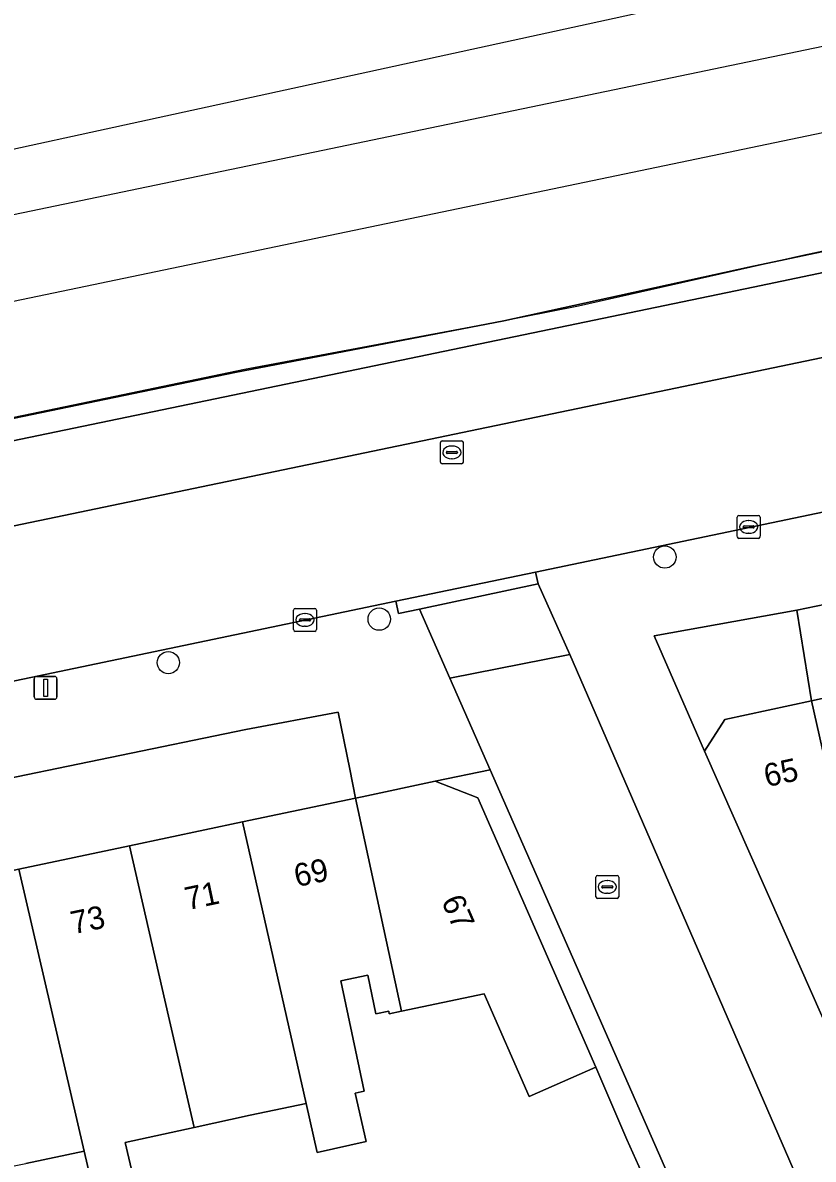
# Model space of a CAD drawing. Extents: x 162989 to 165008, y 383432 to 384338.
# Drawn here: x 163944.51 to 163979.07, y 384118.85 to 384168.55 of the extents above; entities that cross this region are included whole.
import ezdxf

# ---------------------------------------------------------------- set-up
doc = ezdxf.new("R2010")
doc.units = 0
for name, color, linetype in [('IMGEO_Boom', 7, 'Continuous'), ('IMGEO_Erf', 7, 'Continuous'), ('IMGEO_Geluidsscherm', 7, 'Continuous'), ('IMGEO_Groenvoorziening', 7, 'Continuous'), ('IMGEO_Haag', 7, 'Continuous'), ('IMGEO_Kolk', 7, 'Continuous'), ('IMGEO_Lichtmast', 7, 'Continuous'), ('IMGEO_Muur', 7, 'Continuous'), ('IMGEO_Pand', 7, 'Continuous'), ('IMGEO_Pand_nummerreeks', 7, 'Continuous'), ('IMGEO_Rijbaan_lokaal_gesloten', 7, 'Continuous'), ('IMGEO_Rijbaan_lokaal_open', 7, 'Continuous'), ('IMGEO_Rioolput', 7, 'Continuous'), ('IMGEO_Spoor', 7, 'Continuous'), ('IMGEO_Spoorbaan_halfverhard', 7, 'Continuous'), ('IMGEO_Voetpad_open', 7, 'Continuous')]:
    doc.layers.add(name, color=color, linetype=linetype)

msp = doc.modelspace()

# ---------------------------------------------------------------- linework, layer by layer
at = {"layer": 'IMGEO_Boom'}
for centre in [(163972.578, 384145.184), (163960.095, 384142.469), (163950.875, 384140.566)]:
    msp.add_circle(centre, 0.489, dxfattribs=at)
at = {"layer": 'IMGEO_Erf'}
for points in [[(163995.254, 384146.36), (163978.345, 384142.859), (163978.993, 384138.902), (163984.019, 384139.999)], [(163971.837, 384117.672), (163970.917, 384119.717), (163969.555, 384122.869), (163966.652, 384121.592), (163964.675, 384126.085), (163961.062, 384125.322), (163960.533, 384125.21), (163960.508, 384125.33), (163959.948, 384125.212), (163959.592, 384126.897), (163958.417, 384126.649), (163959.436, 384121.826), (163959.046, 384121.744), (163959.524, 384119.624), (163957.381, 384119.14), (163956.896, 384121.289), (163954.452, 384120.772), (163952.011, 384120.238), (163948.994, 384119.582), (163950.338, 384113.794)], [(163948.549, 384113.379), (163947.197, 384119.202), (163944.64, 384118.661)]]:
    msp.add_lwpolyline(points, dxfattribs=at)
for points in [[(163978.345, 384142.859), (163972.112, 384141.733), (163974.316, 384136.7), (163975.198, 384138.074), (163978.993, 384138.902)], [(163949.177, 384132.553), (163954.118, 384133.598), (163959.059, 384134.642), (163958.806, 384135.902), (163958.304, 384138.407), (163954.262, 384137.638), (163924.604, 384131.515), (163926.626, 384127.328), (163929.903, 384128.02), (163929.809, 384128.46), (163934.649, 384129.483), (163939.492, 384130.507), (163944.334, 384131.53)]]:
    msp.add_lwpolyline(points, close=True, dxfattribs=at)
at = {"layer": 'IMGEO_Geluidsscherm'}
msp.add_lwpolyline([(163937.597, 384149.952), (163949.238, 384152.367), (163954.207, 384153.399), (163965.198, 384155.461), (163968.809, 384156.168), (163978.614, 384158.383), (163993.212, 384161.496), (164003.071, 384163.567), (164007.919, 384164.566), (164017.762, 384166.559), (164027.578, 384168.478), (164032.408, 384169.426)], dxfattribs=at)
at = {"layer": 'IMGEO_Groenvoorziening'}
for points in [[(163892.745, 384139.603), (163976.433, 384156.982), (164073.867, 384177.406), (164173.737, 384197.907), (164238.498, 384211.23), (164245.279, 384212.748), (164245.015, 384213.611), (164238.302, 384212.109), (164224.204, 384209.495), (164191.357, 384202.662), (164184.194, 384201.103), (164173.545, 384198.786), (164138.86, 384191.809), (164106.067, 384184.851), (164073.689, 384178.288), (164040.716, 384171.257), (164027.429, 384168.427), (164008.211, 384164.605), (163976.248, 384157.863), (163965.539, 384155.519), (163953.785, 384153.248), (163943.293, 384151.084)], [(164073.867, 384177.406), (163976.433, 384156.982), (163892.745, 384139.603)], [(163916.336, 384140.767), (163989.771, 384156.06), (164000, 384158.405), (164008.393, 384160.13), (164013.045, 384161.087), (164068.214, 384172.427)]]:
    msp.add_lwpolyline(points, dxfattribs=at)
at = {"layer": 'IMGEO_Haag'}
msp.add_lwpolyline([(163892.745, 384139.603), (163976.433, 384156.982), (164073.867, 384177.406), (164173.737, 384197.907), (164238.498, 384211.23), (164245.279, 384212.748), (164245.015, 384213.611), (164238.302, 384212.109), (164224.204, 384209.495), (164191.357, 384202.662), (164184.194, 384201.103), (164173.545, 384198.786), (164138.86, 384191.809), (164106.067, 384184.851), (164073.689, 384178.288), (164040.716, 384171.257), (164027.429, 384168.427), (164008.211, 384164.605), (163976.248, 384157.863), (163965.539, 384155.519), (163953.785, 384153.248), (163943.293, 384151.084)], dxfattribs=at)
at = {"layer": 'IMGEO_Kolk'}
for p, q in [((163975.743, 384146.075), (163975.743, 384146.927)), ((163975.818, 384147.001), (163976.67, 384147.001)), ((163976.231, 384146.781), (163976.256, 384146.781)), ((163976.744, 384146.927), (163976.744, 384146.075)), ((163976.002, 384146.495), (163976.002, 384146.507)), ((163976.44, 384146.458), (163976.042, 384146.458)), ((163976.045, 384146.544), (163976.443, 384146.544)), ((163976.486, 384146.507), (163976.486, 384146.495)), ((163976.67, 384146.001), (163975.818, 384146.001)), ((163976.254, 384146.221), (163976.229, 384146.221)), ((163956.347, 384142.009), (163956.347, 384142.861)), ((163956.422, 384142.935), (163957.274, 384142.935)), ((163957.348, 384142.861), (163957.348, 384142.009)), ((163956.606, 384142.429), (163956.606, 384142.441)), ((163957.044, 384142.392), (163956.646, 384142.392)), ((163956.649, 384142.478), (163957.047, 384142.478)), ((163956.835, 384142.715), (163956.86, 384142.715)), ((163957.09, 384142.441), (163957.09, 384142.429)), ((163957.274, 384141.935), (163956.422, 384141.935)), ((163956.858, 384142.155), (163956.833, 384142.155)), ((163969.562, 384130.332), (163969.562, 384131.184)), ((163969.637, 384131.258), (163970.489, 384131.258)), ((163970.05, 384131.038), (163970.075, 384131.038)), ((163970.563, 384131.184), (163970.563, 384130.332)), ((163969.821, 384130.752), (163969.821, 384130.764)), ((163970.259, 384130.715), (163969.861, 384130.715)), ((163969.864, 384130.801), (163970.262, 384130.801)), ((163970.073, 384130.478), (163970.048, 384130.478)), ((163970.305, 384130.764), (163970.305, 384130.752)), ((163970.489, 384130.258), (163969.637, 384130.258))]:
    msp.add_line(p, q, dxfattribs=at)
for points in [[(163975.743, 384146.075), (163975.743, 384146.927)], [(163975.818, 384147.001), (163976.67, 384147.001)], [(163976.744, 384146.927), (163976.744, 384146.075)], [(163976.67, 384146.001), (163975.818, 384146.001)], [(163956.347, 384142.009), (163956.347, 384142.861)], [(163956.422, 384142.935), (163957.274, 384142.935)], [(163957.348, 384142.861), (163957.348, 384142.009)], [(163957.274, 384141.935), (163956.422, 384141.935)], [(163969.562, 384130.332), (163969.562, 384131.184)], [(163969.637, 384131.258), (163970.489, 384131.258)], [(163970.563, 384131.184), (163970.563, 384130.332)], [(163970.489, 384130.258), (163969.637, 384130.258)]]:
    msp.add_lwpolyline(points, dxfattribs=at)
for centre, radius, start, end in [((163975.82, 384146.925), 0.0765, 91.552, 178.448), ((163975.82, 384146.925), 0.0765, 91.552, 178.448), ((163976.668, 384146.925), 0.0765, 1.552, 88.448), ((163976.668, 384146.925), 0.0765, 1.552, 88.448), ((163976.042, 384146.504), 0.0403, 85.8775, 175.7526), ((163976.039, 384146.494), 0.0366, 178.938, 274.7102), ((163976.443, 384146.501), 0.043, 264.8664, 352.4533), ((163976.447, 384146.506), 0.0386, 1.7309, 96.639), ((163975.82, 384146.077), 0.0765, 181.552, 268.448), ((163975.82, 384146.077), 0.0765, 181.552, 268.448), ((163976.668, 384146.077), 0.0765, 271.552, 358.448), ((163976.668, 384146.077), 0.0765, 271.552, 358.448), ((163956.424, 384142.859), 0.0765, 91.552, 178.448), ((163956.424, 384142.859), 0.0765, 91.552, 178.448), ((163957.272, 384142.859), 0.0765, 1.552, 88.448), ((163957.272, 384142.859), 0.0765, 1.552, 88.448), ((163956.646, 384142.438), 0.0403, 85.8775, 175.7526), ((163956.643, 384142.428), 0.0366, 178.938, 274.7102), ((163957.047, 384142.435), 0.043, 264.8664, 352.4533), ((163957.051, 384142.44), 0.0386, 1.7309, 96.639), ((163956.424, 384142.011), 0.0765, 181.552, 268.448), ((163956.424, 384142.011), 0.0765, 181.552, 268.448), ((163957.272, 384142.011), 0.0765, 271.552, 358.448), ((163957.272, 384142.011), 0.0765, 271.552, 358.448), ((163969.639, 384131.182), 0.0765, 91.552, 178.448), ((163969.639, 384131.182), 0.0765, 91.552, 178.448), ((163970.487, 384131.182), 0.0765, 1.552, 88.448), ((163970.487, 384131.182), 0.0765, 1.552, 88.448), ((163969.861, 384130.761), 0.0403, 85.8775, 175.7526), ((163969.858, 384130.751), 0.0366, 178.938, 274.7102), ((163970.262, 384130.758), 0.043, 264.8664, 352.4533), ((163970.266, 384130.763), 0.0386, 1.7309, 96.639), ((163969.639, 384130.334), 0.0765, 181.552, 268.448), ((163969.639, 384130.334), 0.0765, 181.552, 268.448), ((163970.487, 384130.334), 0.0765, 271.552, 358.448), ((163970.487, 384130.334), 0.0765, 271.552, 358.448)]:
    msp.add_arc(centre, radius, start, end, dxfattribs=at)
for centre, major_axis, ratio, start_param, end_param in [((163976.23, 384146.501), (-0.387, 0.002), 0.722429, 4.712389, 7.853982), ((163976.255, 384146.501), (-0.39, 0.002), 0.717154, 1.570796, 4.712389), ((163956.834, 384142.435), (-0.387, 0.002), 0.722429, 4.712389, 7.853982), ((163956.859, 384142.435), (-0.39, 0.002), 0.717154, 1.570796, 4.712389), ((163970.049, 384130.758), (-0.387, 0.002), 0.722429, 4.712389, 7.853982), ((163970.074, 384130.758), (-0.39, 0.002), 0.717154, 1.570796, 4.712389)]:
    msp.add_ellipse(centre, major_axis=major_axis, ratio=ratio, start_param=start_param, end_param=end_param, dxfattribs=at)
at = {"layer": 'IMGEO_Lichtmast'}
for p, q in [((163945.017, 384139.065), (163945.017, 384139.865)), ((163945.017, 384139.865), (163945.017, 384139.065)), ((163945.117, 384139.965), (163945.907, 384139.965)), ((163945.907, 384139.965), (163945.117, 384139.965)), ((163946.007, 384139.865), (163946.007, 384139.065)), ((163946.007, 384139.065), (163946.007, 384139.865)), ((163945.907, 384138.965), (163945.117, 384138.965)), ((163945.117, 384138.965), (163945.907, 384138.965))]:
    msp.add_line(p, q, dxfattribs=at)
msp.add_lwpolyline([(163945.437, 384139.84), (163945.587, 384139.84), (163945.587, 384139.09), (163945.437, 384139.09), (163945.437, 384139.84)], dxfattribs=at)
for centre, start, end in [((163945.117, 384139.865), 90, 180), ((163945.117, 384139.865), 90, 180), ((163945.907, 384139.865), 0, 90), ((163945.907, 384139.865), 360, 90), ((163945.117, 384139.065), 180, 270), ((163945.117, 384139.065), 180, 270), ((163945.907, 384139.065), 270, 0), ((163945.907, 384139.065), 270, 0)]:
    msp.add_arc(centre, 0.1, start, end, dxfattribs=at)
at = {"layer": 'IMGEO_Muur'}
msp.add_lwpolyline([(163970.917, 384119.717), (163969.555, 384122.869)], dxfattribs=at)
at = {"layer": 'IMGEO_Pand'}
for points in [[(163978.993, 384138.902), (163981.792, 384126.471), (163982.507, 384126.59), (163983.979, 384126.835), (163984.175, 384126.868), (163983.735, 384128.885), (163986.074, 384129.395), (163984.973, 384135.075), (163984.019, 384139.999)], [(163978.993, 384138.902), (163975.198, 384138.074), (163974.316, 384136.7), (163979.046, 384126.015), (163981.004, 384121.592), (163984.214, 384122.729), (163982.507, 384126.59), (163981.792, 384126.471)], [(163961.062, 384125.322), (163964.675, 384126.085), (163966.652, 384121.592), (163969.555, 384122.869), (163964.399, 384134.653), (163962.536, 384135.377), (163959.347, 384134.703), (163959.059, 384134.642)], [(163959.059, 384134.642), (163954.118, 384133.598), (163956.896, 384121.289), (163957.381, 384119.14), (163959.524, 384119.624), (163959.046, 384121.744), (163959.436, 384121.826), (163958.417, 384126.649), (163959.592, 384126.897), (163959.948, 384125.212), (163960.508, 384125.33), (163960.533, 384125.21), (163961.062, 384125.322)], [(163956.896, 384121.289), (163954.118, 384133.598), (163949.177, 384132.553), (163950.89, 384125.108), (163952.011, 384120.238), (163954.452, 384120.772)], [(163949.177, 384132.553), (163944.334, 384131.53), (163947.197, 384119.202), (163948.549, 384113.379), (163950.338, 384113.794), (163948.994, 384119.582), (163952.011, 384120.238), (163950.89, 384125.108)], [(163939.492, 384130.507), (163941.215, 384123.033), (163942.328, 384118.204), (163944.64, 384118.661), (163947.197, 384119.202), (163944.334, 384131.53)]]:
    msp.add_lwpolyline(points, close=True, dxfattribs=at)
at = {"layer": 'IMGEO_Rijbaan_lokaal_gesloten'}
msp.add_lwpolyline([(163923.113, 384135.366), (163960.826, 384143.251), (163966.926, 384144.526), (163982.743, 384147.834), (163986.464, 384148.612), (163997.553, 384150.93), (164000, 384151.442), (164001.293, 384151.706), (164009.768, 384153.438), (164008.393, 384160.13), (164000, 384158.405), (163989.771, 384156.06), (163916.336, 384140.767), (163911.749, 384139.874), (163913.038, 384133.253), (163917.195, 384134.125)], close=True, dxfattribs=at)
at = {"layer": 'IMGEO_Rijbaan_lokaal_open'}
msp.add_lwpolyline([(163968.422, 384140.927), (163963.186, 384139.88), (163964.941, 384135.885), (163977.753, 384106.722), (163978.881, 384101.326), (163977.556, 384101.07), (163973.97, 384100.353), (163970.383, 384099.636), (163966.797, 384098.92), (163963.375, 384098.236), (163959.954, 384097.552), (163956.532, 384096.868), (163953.111, 384096.184), (163949.689, 384095.5), (163946.267, 384094.816), (163945.04, 384094.571), (163946.672, 384086.586), (163955.483, 384088.354), (163978.057, 384092.882), (163980.946, 384093.461), (163983.835, 384094.041), (163986.724, 384094.62), (163985.215, 384102.252)], close=True, dxfattribs=at)
at = {"layer": 'IMGEO_Rioolput'}
for p, q in [((163962.844, 384150.26), (163963.696, 384150.26)), ((163962.769, 384149.334), (163962.769, 384150.186)), ((163963.028, 384149.754), (163963.028, 384149.766)), ((163963.071, 384149.803), (163963.469, 384149.803)), ((163963.257, 384150.04), (163963.282, 384150.04)), ((163963.512, 384149.766), (163963.512, 384149.754)), ((163963.77, 384150.186), (163963.77, 384149.334)), ((163963.696, 384149.26), (163962.844, 384149.26)), ((163963.466, 384149.717), (163963.068, 384149.717)), ((163963.28, 384149.48), (163963.255, 384149.48))]:
    msp.add_line(p, q, dxfattribs=at)
for points in [[(163962.844, 384150.26), (163963.696, 384150.26)], [(163962.769, 384149.334), (163962.769, 384150.186)], [(163963.77, 384150.186), (163963.77, 384149.334)], [(163963.696, 384149.26), (163962.844, 384149.26)]]:
    msp.add_lwpolyline(points, dxfattribs=at)
for centre, radius, start, end in [((163962.846, 384150.184), 0.0765, 91.552, 178.448), ((163962.846, 384150.184), 0.0765, 91.552, 178.448), ((163963.694, 384150.184), 0.0765, 1.552, 88.448), ((163963.694, 384150.184), 0.0765, 1.552, 88.448), ((163963.068, 384149.763), 0.0403, 85.8775, 175.7526), ((163963.065, 384149.753), 0.0366, 178.938, 274.7102), ((163963.469, 384149.76), 0.043, 264.8664, 352.4533), ((163963.473, 384149.765), 0.0386, 1.7309, 96.639), ((163962.846, 384149.336), 0.0765, 181.552, 268.448), ((163962.846, 384149.336), 0.0765, 181.552, 268.448), ((163963.694, 384149.336), 0.0765, 271.552, 358.448), ((163963.694, 384149.336), 0.0765, 271.552, 358.448)]:
    msp.add_arc(centre, radius, start, end, dxfattribs=at)
for centre, major_axis, ratio, start_param, end_param in [((163963.256, 384149.76), (-0.387, 0.002), 0.722429, 4.712389, 7.853982), ((163963.281, 384149.76), (-0.39, 0.002), 0.717154, 1.570796, 4.712389)]:
    msp.add_ellipse(centre, major_axis=major_axis, ratio=ratio, start_param=start_param, end_param=end_param, dxfattribs=at)
at = {"layer": 'IMGEO_Spoor'}
for points in [[(164788.231, 384335.773), (164684.182, 384314.23), (164649.743, 384306.978), (164549.034, 384286.117), (164446.504, 384264.637), (164353.435, 384245.24), (164284.243, 384230.902), (164214.646, 384216.358), (164173.585, 384207.909), (164102.605, 384193.066), (164031.754, 384178.409), (163810.752, 384132.353), (163673.071, 384103.86), (163574.904, 384083.455)], [(164789.572, 384332.389), (164775.58, 384329.429), (164644.744, 384302.256), (164570.629, 384286.722), (164345.336, 384239.894), (164220.116, 384213.747), (164092.662, 384187.275), (164071.527, 384182.957), (163942.979, 384156.119), (163900.983, 384147.477), (163806.025, 384127.659), (163575.669, 384079.775)]]:
    msp.add_lwpolyline(points, dxfattribs=at)
at = {"layer": 'IMGEO_Spoorbaan_halfverhard'}
for points in [[(164064.865, 384189.352), (163941.114, 384162.363)], [(163943.293, 384151.084), (163953.785, 384153.248), (163965.539, 384155.519), (163976.248, 384157.863), (164008.211, 384164.605), (164027.429, 384168.427), (164040.716, 384171.257)]]:
    msp.add_lwpolyline(points, dxfattribs=at)
at = {"layer": 'IMGEO_Voetpad_open'}
for points in [[(164015.858, 384154.683), (164014.422, 384154.39), (164009.768, 384153.438), (164001.293, 384151.706), (164001.383, 384151.265), (163997.645, 384150.49), (163997.553, 384150.93), (163986.464, 384148.612), (163986.561, 384148.141), (163982.84, 384147.366), (163982.743, 384147.834), (163966.926, 384144.526), (163967.036, 384144.011), (163968.422, 384140.927), (163985.215, 384102.252), (163986.724, 384094.62), (163988.027, 384088.819)], [(163989.701, 384089.167), (163988.61, 384094.965), (163986.606, 384105.606), (163986.047, 384106.81), (163985.247, 384108.534), (163986.671, 384108.791), (163986.018, 384110.266), (163983.777, 384115.329), (163981.004, 384121.592), (163979.046, 384126.015), (163974.316, 384136.7), (163972.112, 384141.733), (163978.345, 384142.859), (163995.254, 384146.36)]]:
    msp.add_lwpolyline(points, dxfattribs=at)
for points in [[(163967.036, 384144.011), (163966.926, 384144.526), (163960.826, 384143.251), (163960.94, 384142.716), (163961.855, 384142.91)], [(163967.036, 384144.011), (163961.855, 384142.91), (163963.186, 384139.88), (163968.422, 384140.927)], [(163958.304, 384138.407), (163958.806, 384135.902), (163959.059, 384134.642), (163959.347, 384134.703), (163962.536, 384135.377), (163964.941, 384135.885), (163963.186, 384139.88), (163961.855, 384142.91), (163960.94, 384142.716), (163960.826, 384143.251), (163923.113, 384135.366), (163923.697, 384131.328), (163924.604, 384131.515), (163954.262, 384137.638)], [(163964.941, 384135.885), (163962.536, 384135.377), (163964.399, 384134.653), (163969.555, 384122.869), (163970.917, 384119.717), (163971.837, 384117.672), (163973.296, 384114.375), (163974.756, 384111.079), (163976.215, 384107.782), (163977.556, 384101.07), (163978.881, 384101.326), (163977.753, 384106.722)]]:
    msp.add_lwpolyline(points, close=True, dxfattribs=at)

# ---------------------------------------------------------------- texts
at = {"layer": 'IMGEO_Pand_nummerreeks'}
for s, rotation, p in [('65', 12.3096, (163977.029, 384135.117)), ('69', 11.9347, (163956.487, 384130.746)), ('71', 11.9341, (163951.715, 384129.738)), ('67', 293.6314, (163962.791, 384130.147)), ('73', 11.9347, (163946.723, 384128.682))]:
    msp.add_text(s, height=1, rotation=rotation, dxfattribs=at).set_placement(p)

doc.saveas('drawing.dxf')
